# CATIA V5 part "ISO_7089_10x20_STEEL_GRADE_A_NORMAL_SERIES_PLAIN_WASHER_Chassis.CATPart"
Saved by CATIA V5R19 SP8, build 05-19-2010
Part number: ISO 7089 WASHER 10x20 STEEL GRADE A PLAIN NORMAL SERIES
Nomenclature: 34
Publications: "Mating Face", "Axis"
Bounding box of the stored display mesh (mm): x 0 to 2, y -10 to 10, z -10 to 10
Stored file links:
  C:\Users\rphgr\Desktop\0_Tapis_TC520B_vitesse\ISO_7089_10x20_STEEL_GRADE_A_NORMAL_SERIES_PLAIN_WASHER_Chassis.CATPart
  D:\Programmes\DassaultSysteme\win_b64\startup\components\MechanicalStandardParts\ISO_Standards\Design_Tables\ISO_7089_PLAIN_WASHER_GRADE_A_NORMAL_SERIES.txt
  C:\Program Files\Dassault Systemes\B19\win_b64\startup\components\MechanicalStandardParts\ISO_Standards\Design_Tables\ISO_7089_PLAIN_WASHER_GRADE_A_NORMAL_SERIES.txt
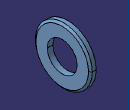
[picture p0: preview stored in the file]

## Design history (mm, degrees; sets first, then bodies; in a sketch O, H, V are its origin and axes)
Parameters
  d1_inside_dia = 10.5 mm
  d2_outside_dia = 20 mm
  h_thick = 2 mm
  Nominal_dia = 10 mm
Body1 "PartBody" (main body)
  Sketch1 on yz-plane, origin (0, 0, 0), H (0, 1, 0), V (0, 0, 1)
    circle A1 centre (0, 0) radius 10
    circle A2 centre (0, 0) radius 5.25
    radius A1 = 10 {= d2_outside_dia /2}
    radius A2 = 5.25 {= d1_inside_dia /2}
  Pad1: profile Sketch1, direction (1, 0, 0), length 2 {= h_thick}
  Chamfer1: length 0.75 {= 0.375*h_thick}, angle 37.5, on edge [face of Pad1 | face of Pad1]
